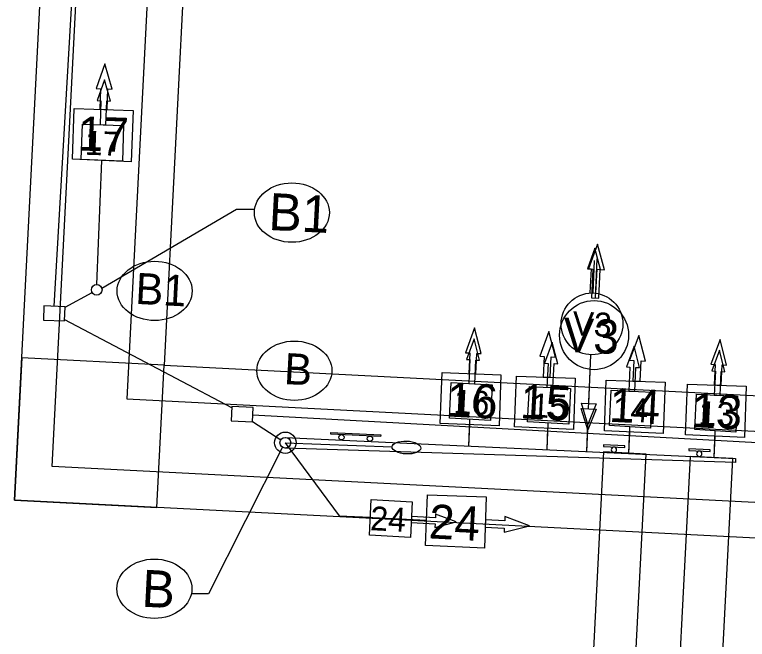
# Model space of a CAD drawing. Extents: x 21 to 686546, y 24 to 735466.
# Drawn here: x 680884.5 to 680987.4, y 735043.2 to 735130.9 of the extents above; entities that cross this region are included whole.
import ezdxf

# ---------------------------------------------------------------- set-up
doc = ezdxf.new("R2010")
doc.units = 0
for name, color, linetype in [('PEDXLIMITS-PR', 7, 'Continuous'), ('signal wiring diagram', 7, 'Continuous'), ('SIGNAL-PLAN VIEW LABLES', 7, 'Continuous'), ('SIGNAL-PR', 7, 'Continuous'), ('signal-pr-conduit', 7, 'Continuous'), ('Video-Zones-pr', 7, 'Continuous')]:
    doc.layers.add(name, color=color, linetype=linetype)

# ---------------------------------------------------------------- blocks, each defined once
blk = doc.blocks.new('STREET NAME SIGN')
at = {"layer": 'SIGNAL-PR'}
blk.add_lwpolyline([(1.5, 0.96), (1.49, 0.71), (-5.5, 0.9), (-5.5, 1.15)], close=True, dxfattribs=at)
for centre in [(-4, 0.49), (-0.01, 0.37)]:
    blk.add_circle(centre, 0.375, dxfattribs=at)
blk = doc.blocks.new('R10-12 SIGN')
at = {"layer": 'SIGNAL-PR'}
blk.add_lwpolyline([(1.52, 0.75), (-1.48, 0.75), (-1.48, 1), (1.52, 1), (1.52, 0.75)], close=True, dxfattribs=at)
blk.add_circle((0.02, 0.37), 0.375, dxfattribs=at)

msp = doc.modelspace()

# ---------------------------------------------------------------- linework, layer by layer
at = {"layer": 'PEDXLIMITS-PR'}
for points in [[(681056.26, 735053.96), (680884.52, 735062.77), (680892.76, 735223.49), (681064.67, 735216.71)], [(681051.53, 735059.21), (680889.77, 735067.5), (680897.5, 735218.3), (681059.42, 735211.91)], [(680906.98, 735207.92), (680900.27, 735076.98), (681042.06, 735069.71), (681048.91, 735202.32)], [(680911.72, 735202.73), (680905.52, 735081.72), (681037.32, 735074.96), (681043.65, 735197.52)], [(680905.52, 735081.72), (680885.54, 735082.74), (680884.52, 735062.77), (680904.49, 735061.74)]]:
    msp.add_lwpolyline(points, close=True, dxfattribs=at)
at = {"layer": 'signal wiring diagram'}
for p, q in [((680922.54, 735070.83), (680930.1, 735060.58)), ((680930.1, 735060.58), (680934.47, 735060.36)), ((680940.24, 735060.06), (680942.38, 735059.95))]:
    msp.add_line(p, q, dxfattribs=at)
for points in [[(680897.46, 735118.83), (680897.96, 735118.82), (680897.13, 735121.8), (680896.11, 735118.88), (680896.62, 735118.86), (680896.51, 735115.5), (680897.35, 735115.48), (680897.46, 735118.83)], [(680897.35, 735115.48), (680897.46, 735118.83), (680897.96, 735118.82), (680897.13, 735121.8), (680896.11, 735118.88), (680896.62, 735118.86), (680896.51, 735115.5)], [(680896.08, 735093.06), (680896.77, 735110.48)], [(680966.32, 735095.2), (680966.82, 735095.18), (680966.03, 735098.16), (680964.97, 735095.26), (680965.48, 735095.24), (680965.32, 735091.88), (680966.16, 735091.84), (680966.32, 735095.2)], [(680966.16, 735091.84), (680966.32, 735095.2), (680966.82, 735095.18), (680966.03, 735098.16), (680964.97, 735095.26), (680965.48, 735095.24), (680965.32, 735091.88)], [(680965.78, 735091.86), (680965.96, 735096.44)], [(680949.31, 735082.45), (680949.82, 735082.43), (680949.05, 735085.42), (680947.97, 735082.52), (680948.47, 735082.5), (680948.3, 735079.14), (680949.14, 735079.1), (680949.31, 735082.45)], [(680949.14, 735079.1), (680949.31, 735082.45), (680949.82, 735082.43), (680949.05, 735085.42), (680947.97, 735082.52), (680948.47, 735082.5), (680948.3, 735079.14)], [(680960.3, 735081.94), (680960.81, 735081.91), (680960.03, 735084.91), (680958.96, 735082.01), (680959.46, 735081.98), (680959.29, 735078.63), (680960.13, 735078.58), (680960.3, 735081.94)], [(680960.13, 735078.58), (680960.3, 735081.94), (680960.81, 735081.91), (680960.03, 735084.91), (680958.96, 735082.01), (680959.46, 735081.98), (680959.29, 735078.63)], [(680971.79, 735081.4), (680972.29, 735081.38), (680971.52, 735084.37), (680970.45, 735081.47), (680970.95, 735081.44), (680970.78, 735078.09), (680971.62, 735078.05), (680971.79, 735081.4)], [(680971.62, 735078.05), (680971.79, 735081.4), (680972.29, 735081.38), (680971.52, 735084.37), (680970.45, 735081.47), (680970.95, 735081.44), (680970.78, 735078.09)], [(680983.78, 735080.84), (680984.28, 735080.81), (680983.51, 735083.81), (680982.43, 735080.91), (680982.94, 735080.88), (680982.77, 735077.53), (680983.6, 735077.48), (680983.78, 735080.84)], [(680983.6, 735077.48), (680983.78, 735080.84), (680984.28, 735080.81), (680983.51, 735083.81), (680982.43, 735080.91), (680982.94, 735080.88), (680982.77, 735077.53)], [(680965.17, 735076.33), (680965.44, 735083.18)], [(680948.32, 735070.37), (680948.46, 735074.11)], [(680959.31, 735069.86), (680959.45, 735073.59)], [(680964.91, 735069.6), (680965.05, 735073.37)], [(680970.79, 735069.32), (680970.94, 735073.06)], [(680982.78, 735068.76), (680982.93, 735072.5)], [(680943.57, 735059.44), (680943.55, 735058.94), (680946.54, 735059.71), (680943.64, 735060.79), (680943.62, 735060.28), (680940.26, 735060.45), (680940.22, 735059.62), (680943.57, 735059.44)], [(680940.22, 735059.62), (680943.57, 735059.44), (680943.55, 735058.94), (680946.54, 735059.71), (680943.64, 735060.79), (680943.62, 735060.28), (680940.26, 735060.45)]]:
    msp.add_lwpolyline(points, dxfattribs=at)
for points in [[(680893.88, 735110.59), (680894.04, 735115.58), (680899.82, 735115.4), (680899.66, 735110.36)], [(680945.58, 735074.28), (680945.84, 735079.27), (680951.61, 735078.97), (680951.35, 735073.94)], [(680956.57, 735073.77), (680956.83, 735078.75), (680962.6, 735078.46), (680962.34, 735073.42)], [(680968.06, 735073.23), (680968.31, 735078.22), (680974.08, 735077.92), (680973.83, 735072.89)], [(680980.04, 735072.67), (680980.3, 735077.65), (680986.07, 735077.36), (680985.81, 735072.32)], [(680965.05, 735073.37), (680964.13, 735076.38), (680966.21, 735076.28)], [(680934.34, 735057.86), (680934.6, 735062.85), (680940.37, 735062.55), (680940.11, 735057.52)]]:
    msp.add_lwpolyline(points, close=True, dxfattribs=at)
msp.add_circle((680965.61, 735087.52), 4.34, dxfattribs=at)
for centre in [(680904.18, 735092.15), (680923.81, 735080.95)]:
    msp.add_ellipse(centre, major_axis=(-5.27, 0), ratio=0.790685, dxfattribs=at)
at = {"layer": 'SIGNAL-PLAN VIEW LABLES'}
for p, q in [((680897.2, 735124.06), (680895.98, 735120.56)), ((680898.2, 735120.49), (680897.2, 735124.06)), ((680895.98, 735120.56), (680896.59, 735120.54)), ((680896.59, 735120.54), (680896.49, 735117.66)), ((680897.5, 735117.63), (680897.59, 735120.51)), ((680897.59, 735120.51), (680898.2, 735120.49)), ((680896.49, 735117.66), (680897.5, 735117.63)), ((680949.13, 735086.95), (680947.84, 735083.47)), ((680950.06, 735083.35), (680949.13, 735086.95)), ((680959.57, 735086.45), (680958.28, 735082.98)), ((680960.5, 735082.86), (680959.57, 735086.45)), ((680972.19, 735085.89), (680970.9, 735082.41)), ((680973.12, 735082.3), (680972.19, 735085.89)), ((680983.6, 735085.33), (680982.31, 735081.85)), ((680984.52, 735081.74), (680983.6, 735085.33)), ((680947.84, 735083.47), (680948.45, 735083.44)), ((680948.45, 735083.44), (680948.3, 735080.55)), ((680949.31, 735080.52), (680949.45, 735083.38)), ((680949.45, 735083.38), (680950.06, 735083.35)), ((680958.28, 735082.98), (680958.89, 735082.95)), ((680958.89, 735082.95), (680958.74, 735080.06)), ((680959.75, 735080.03), (680959.89, 735082.89)), ((680959.89, 735082.89), (680960.5, 735082.86)), ((680970.9, 735082.41), (680971.51, 735082.38)), ((680971.51, 735082.38), (680971.36, 735079.5)), ((680972.36, 735079.46), (680972.51, 735082.33)), ((680972.51, 735082.33), (680973.12, 735082.3)), ((680982.31, 735081.85), (680982.91, 735081.82)), ((680982.91, 735081.82), (680982.76, 735078.94)), ((680983.77, 735078.9), (680983.92, 735081.77)), ((680983.92, 735081.77), (680984.52, 735081.74)), ((680948.3, 735080.55), (680949.31, 735080.52)), ((680958.74, 735080.06), (680959.75, 735080.03)), ((680971.36, 735079.5), (680972.36, 735079.46)), ((680982.76, 735078.94), (680983.77, 735078.9)), ((680922.54, 735070.83), (680930.1, 735060.58)), ((680930.1, 735060.58), (680942.38, 735059.95)), ((680950.64, 735060), (680950.61, 735058.99)), ((680953.35, 735059.86), (680950.64, 735060)), ((680953.38, 735060.46), (680953.35, 735059.86)), ((680956.86, 735059.17), (680953.38, 735060.46)), ((680950.61, 735058.99), (680953.3, 735058.85)), ((680953.27, 735058.25), (680956.86, 735059.17)), ((680953.3, 735058.85), (680953.27, 735058.25))]:
    msp.add_line(p, q, dxfattribs=at)
for points in [[(680897.5, 735117.63), (680897.59, 735120.51), (680898.2, 735120.49), (680897.2, 735124.06), (680895.98, 735120.56), (680896.59, 735120.54), (680896.49, 735117.66)], [(680896.08, 735093.06), (680896.77, 735110.48)], [(680896.76, 735092.54), (680915.69, 735103.65), (680918.24, 735103.65)], [(680966.74, 735095.16), (680967.35, 735095.13), (680966.4, 735098.72), (680965.13, 735095.23), (680965.73, 735095.21), (680965.55, 735091.18), (680966.56, 735091.13), (680966.74, 735095.16)], [(680966.56, 735091.13), (680966.74, 735095.16), (680967.35, 735095.13), (680966.4, 735098.72), (680965.13, 735095.23), (680965.73, 735095.21), (680965.55, 735091.18)], [(680966.1, 735091.15), (680966.32, 735096.64)], [(680949.31, 735080.52), (680949.45, 735083.38), (680950.06, 735083.35), (680949.13, 735086.95), (680947.84, 735083.47), (680948.45, 735083.44), (680948.3, 735080.55)], [(680959.75, 735080.03), (680959.89, 735082.89), (680960.5, 735082.86), (680959.57, 735086.45), (680958.28, 735082.98), (680958.89, 735082.95), (680958.74, 735080.06)], [(680972.36, 735079.46), (680972.51, 735082.33), (680973.12, 735082.3), (680972.19, 735085.89), (680970.9, 735082.41), (680971.51, 735082.38), (680971.36, 735079.5)], [(680983.77, 735078.9), (680983.92, 735081.77), (680984.52, 735081.74), (680983.6, 735085.33), (680982.31, 735081.85), (680982.91, 735081.82), (680982.76, 735078.94)], [(680965.14, 735075.59), (680965.35, 735080.76)], [(680948.32, 735070.37), (680948.44, 735073.37)], [(680959.31, 735069.86), (680959.42, 735072.86)], [(680964.91, 735069.6), (680965.03, 735072.64)], [(680970.79, 735069.32), (680970.91, 735072.32)], [(680982.78, 735068.76), (680982.9, 735071.76)], [(680922.14, 735070.2), (680911.77, 735049.62), (680909.33, 735049.62)], [(680950.61, 735058.99), (680953.3, 735058.85), (680953.27, 735058.25), (680956.86, 735059.17), (680953.38, 735060.46), (680953.35, 735059.86), (680950.64, 735060)]]:
    msp.add_lwpolyline(points, dxfattribs=at)
for points in [[(680892.64, 735110.65), (680892.89, 735117.79), (680901.15, 735117.5), (680900.89, 735110.3)], [(680944.31, 735073.55), (680944.56, 735080.68), (680952.81, 735080.39), (680952.56, 735073.19)], [(680954.75, 735073.06), (680955, 735080.19), (680963.25, 735079.9), (680963, 735072.7)], [(680967.37, 735072.5), (680967.61, 735079.63), (680975.87, 735079.34), (680975.62, 735072.14)], [(680978.77, 735071.93), (680979.02, 735079.07), (680987.28, 735078.78), (680987.03, 735071.58)], [(680965.03, 735072.64), (680964.1, 735075.64), (680966.18, 735075.54)], [(680942.25, 735056.38), (680942.5, 735063.51), (680950.76, 735063.23), (680950.5, 735056.03)]]:
    msp.add_lwpolyline(points, close=True, dxfattribs=at)
msp.add_circle((680965.9, 735085.94), 4.85, dxfattribs=at)
for centre in [(680923.46, 735103.15), (680904.15, 735050.33)]:
    msp.add_ellipse(centre, major_axis=(-5.27, 0), ratio=0.790685, dxfattribs=at)
at = {"layer": 'SIGNAL-PR'}
msp.add_line((680922.54, 735070.83), (680937.53, 735070.24), dxfattribs=at)
for points in [[(680888.55, 735088.06), (680891.54, 735087.93), (680891.63, 735089.92), (680888.64, 735090.06)], [(680914.92, 735073.9), (680917.92, 735073.76), (680918.01, 735075.76), (680915.01, 735075.9)]]:
    msp.add_lwpolyline(points, close=True, dxfattribs=at)
msp.add_lwpolyline([(680922.58, 735071.58), (680985.78, 735068.62), (680985.76, 735068.05), (680922.52, 735070.08)], dxfattribs=at)
for centre, radius in [((680896.05, 735092.31), 0.75), ((680922.54, 735070.83), 1.5), ((680922.54, 735070.83), 0.75)]:
    msp.add_circle(centre, radius, dxfattribs=at)
msp.add_ellipse((680939.55, 735070.16), major_axis=(-2.02, 0.08), ratio=0.447722, dxfattribs=at)
at = {"layer": 'signal-pr-conduit'}
for points in [[(680895.79, 735189.1), (680890.03, 735090)], [(680891.63, 735089.87), (680895.41, 735091.92)], [(680915.01, 735075.75), (680891.55, 735088.07)], [(680917.96, 735074.75), (681028.14, 735068.71)], [(680917.92, 735073.83), (680921.93, 735071.25)]]:
    msp.add_lwpolyline(points, dxfattribs=at)
at = {"layer": 'Video-Zones-pr'}
for points in [[(680967.24, 735069.54), (680964.68, 735019.61), (680970.67, 735019.3), (680973.23, 735069.23)], [(680979.4, 735068.92), (680976.84, 735018.98), (680982.84, 735018.68), (680985.39, 735068.61)]]:
    msp.add_lwpolyline(points, close=True, dxfattribs=at)

# ---------------------------------------------------------------- block references
at = {"layer": 'SIGNAL-PR', "rotation": -1.025471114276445}
msp.add_blockref('STREET NAME SIGN', (680934.42, 735071.03), dxfattribs=at)
at = {"layer": 'SIGNAL-PR', "yscale": -1, "rotation": 177.42983234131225}
for p in [(680968.7, 735069.48), (680980.69, 735068.91)]:
    msp.add_blockref('R10-12 SIGN', p, dxfattribs=at)

# ---------------------------------------------------------------- texts
at = {"layer": 'signal wiring diagram'}
for s, height, rotation, p in [('17', 3.36, 358.1438, (680894.34, 735111.28)), ('B1', 4.368, 357.0414, (680901.41, 735090.34)), ('V3', 3.36, 357.4825, (680962.82, 735085.93)), ('B', 4.37, 357.0414, (680922.29, 735079.08)), ('16', 3.36, 357.0414, (680946.13, 735074.95)), ('15', 3.36, 357.0414, (680957.04, 735074.44)), ('14', 3.36, 357.0414, (680968.45, 735073.91)), ('13', 3.36, 357.0414, (680980.52, 735073.34)), ('24', 3.36, 357.0414, (680934.41, 735058.56))]:
    msp.add_text(s, height=height, rotation=rotation, dxfattribs=at).set_placement(p)
at = {"layer": 'SIGNAL-PLAN VIEW LABLES'}
for s, height, rotation, p in [('17', 4.8, 358.1438, (680893.32, 735111.88)), ('B1', 5.2, 357.0414, (680920.11, 735100.72)), ('V3', 4.8, 357.4825, (680961.46, 735083.62)), ('16', 4.8, 357.0414, (680945.11, 735074.53)), ('15', 4.8, 357.0414, (680955.44, 735074.27)), ('14', 4.8, 357.0414, (680967.95, 735073.79)), ('13', 4.8, 357.0414, (680979.46, 735073.05)), ('24', 4.8, 357.0414, (680942.62, 735057.41)), ('B', 5.2, 357.0414, (680902.28, 735047.82))]:
    msp.add_text(s, height=height, rotation=rotation, dxfattribs=at).set_placement(p)

doc.saveas('drawing.dxf')
